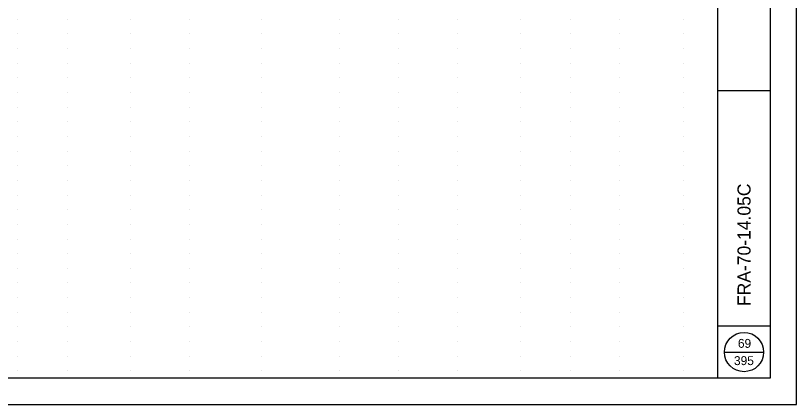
# Model space of a CAD drawing. Extents: x -15.4 to 18.6, y -12.6 to 9.4.
# Drawn here: x 3.72 to 18.64, y -12.61 to -5.18 of the extents above; entities that cross this region are included whole.
import ezdxf

# ---------------------------------------------------------------- set-up
doc = ezdxf.new("R2010")
doc.units = 0
for name, color, linetype in [('SH_Border', 7, 'Continuous'), ('SH_Cut_Line', 7, 'Continuous'), ('SH_Data', 7, 'Continuous')]:
    doc.layers.add(name, color=color, linetype=linetype)

msp = doc.modelspace()

# ---------------------------------------------------------------- linework, layer by layer
at = {"layer": 'SH_Border'}
for p, q in [((17.143, -12.112), (17.143, 8.888)), ((17.143, -6.612), (18.143, -6.612)), ((17.143, -11.112), (18.143, -11.112))]:
    msp.add_line(p, q, dxfattribs=at)
msp.add_lwpolyline([(-13.357, 8.888), (18.143, 8.888), (18.143, -12.112), (-13.357, -12.112)], close=True, dxfattribs=at)
at = {"layer": 'SH_Cut_Line'}
msp.add_lwpolyline([(-15.357, -12.612), (18.643, -12.612), (18.643, 9.388), (-15.357, 9.388)], close=True, dxfattribs=at)
at = {"layer": 'SH_Data'}
for p, q in [((3.768, -5.252), (3.768, -5.252)), ((4.718, -5.252), (4.718, -5.252)), ((5.918, -5.252), (5.918, -5.252)), ((7.043, -5.252), (7.043, -5.252)), ((8.418, -5.252), (8.418, -5.252)), ((9.918, -5.252), (9.918, -5.252)), ((11.043, -5.252), (11.043, -5.252)), ((12.168, -5.252), (12.168, -5.252)), ((13.368, -5.252), (13.368, -5.252)), ((14.318, -5.252), (14.318, -5.252)), ((15.268, -5.252), (15.268, -5.252)), ((16.493, -5.252), (16.493, -5.252)), ((3.768, -5.532), (3.768, -5.532)), ((4.718, -5.532), (4.718, -5.532)), ((5.918, -5.532), (5.918, -5.532)), ((7.043, -5.532), (7.043, -5.532)), ((8.418, -5.532), (8.418, -5.532)), ((9.918, -5.532), (9.918, -5.532)), ((11.043, -5.532), (11.043, -5.532)), ((12.168, -5.532), (12.168, -5.532)), ((13.368, -5.532), (13.368, -5.532)), ((14.318, -5.532), (14.318, -5.532)), ((15.268, -5.532), (15.268, -5.532)), ((16.493, -5.532), (16.493, -5.532)), ((3.768, -5.812), (3.768, -5.812)), ((4.718, -5.812), (4.718, -5.812)), ((5.918, -5.812), (5.918, -5.812)), ((7.043, -5.812), (7.043, -5.812)), ((8.418, -5.812), (8.418, -5.812)), ((9.918, -5.812), (9.918, -5.812)), ((11.043, -5.812), (11.043, -5.812)), ((12.168, -5.812), (12.168, -5.812)), ((13.368, -5.812), (13.368, -5.812)), ((14.318, -5.812), (14.318, -5.812)), ((15.268, -5.812), (15.268, -5.812)), ((16.493, -5.812), (16.493, -5.812)), ((3.768, -6.092), (3.768, -6.092)), ((4.718, -6.092), (4.718, -6.092)), ((5.918, -6.092), (5.918, -6.092)), ((7.043, -6.092), (7.043, -6.092)), ((8.418, -6.092), (8.418, -6.092)), ((9.918, -6.092), (9.918, -6.092)), ((11.043, -6.092), (11.043, -6.092)), ((12.168, -6.092), (12.168, -6.092)), ((13.368, -6.092), (13.368, -6.092)), ((14.318, -6.092), (14.318, -6.092)), ((15.268, -6.092), (15.268, -6.092)), ((16.493, -6.092), (16.493, -6.092)), ((3.768, -6.372), (3.768, -6.372)), ((4.718, -6.372), (4.718, -6.372)), ((5.918, -6.372), (5.918, -6.372)), ((7.043, -6.372), (7.043, -6.372)), ((8.418, -6.372), (8.418, -6.372)), ((9.918, -6.372), (9.918, -6.372)), ((11.043, -6.372), (11.043, -6.372)), ((12.168, -6.372), (12.168, -6.372)), ((13.368, -6.372), (13.368, -6.372)), ((14.318, -6.372), (14.318, -6.372)), ((15.268, -6.372), (15.268, -6.372)), ((16.493, -6.372), (16.493, -6.372)), ((3.768, -6.652), (3.768, -6.652)), ((4.718, -6.652), (4.718, -6.652)), ((5.918, -6.652), (5.918, -6.652)), ((7.043, -6.652), (7.043, -6.652)), ((8.418, -6.652), (8.418, -6.652)), ((9.918, -6.652), (9.918, -6.652)), ((11.043, -6.652), (11.043, -6.652)), ((12.168, -6.652), (12.168, -6.652)), ((13.368, -6.652), (13.368, -6.652)), ((14.318, -6.652), (14.318, -6.652)), ((15.268, -6.652), (15.268, -6.652)), ((16.493, -6.652), (16.493, -6.652)), ((3.768, -6.932), (3.768, -6.932)), ((4.718, -6.932), (4.718, -6.932)), ((5.918, -6.932), (5.918, -6.932)), ((7.043, -6.932), (7.043, -6.932)), ((8.418, -6.932), (8.418, -6.932)), ((9.918, -6.932), (9.918, -6.932)), ((11.043, -6.932), (11.043, -6.932)), ((12.168, -6.932), (12.168, -6.932)), ((13.368, -6.932), (13.368, -6.932)), ((14.318, -6.932), (14.318, -6.932)), ((15.268, -6.932), (15.268, -6.932)), ((16.493, -6.932), (16.493, -6.932)), ((3.768, -7.212), (3.768, -7.212)), ((4.718, -7.212), (4.718, -7.212)), ((5.918, -7.212), (5.918, -7.212)), ((7.043, -7.212), (7.043, -7.212)), ((8.418, -7.212), (8.418, -7.212)), ((9.918, -7.212), (9.918, -7.212)), ((11.043, -7.212), (11.043, -7.212)), ((12.168, -7.212), (12.168, -7.212)), ((13.368, -7.212), (13.368, -7.212)), ((14.318, -7.212), (14.318, -7.212)), ((15.268, -7.212), (15.268, -7.212)), ((16.493, -7.212), (16.493, -7.212)), ((3.768, -7.492), (3.768, -7.492)), ((4.718, -7.492), (4.718, -7.492)), ((5.918, -7.492), (5.918, -7.492)), ((7.043, -7.492), (7.043, -7.492)), ((8.418, -7.492), (8.418, -7.492)), ((9.918, -7.492), (9.918, -7.492)), ((11.043, -7.492), (11.043, -7.492)), ((12.168, -7.492), (12.168, -7.492)), ((13.368, -7.492), (13.368, -7.492)), ((14.318, -7.492), (14.318, -7.492)), ((15.268, -7.492), (15.268, -7.492)), ((16.493, -7.492), (16.493, -7.492)), ((3.768, -7.772), (3.768, -7.772)), ((4.718, -7.772), (4.718, -7.772)), ((5.918, -7.772), (5.918, -7.772)), ((7.043, -7.772), (7.043, -7.772)), ((8.418, -7.772), (8.418, -7.772)), ((9.918, -7.772), (9.918, -7.772)), ((11.043, -7.772), (11.043, -7.772)), ((12.168, -7.772), (12.168, -7.772)), ((13.368, -7.772), (13.368, -7.772)), ((14.318, -7.772), (14.318, -7.772)), ((15.268, -7.772), (15.268, -7.772)), ((16.493, -7.772), (16.493, -7.772)), ((3.768, -8.052), (3.768, -8.052)), ((4.718, -8.052), (4.718, -8.052)), ((5.918, -8.052), (5.918, -8.052)), ((7.043, -8.052), (7.043, -8.052)), ((8.418, -8.052), (8.418, -8.052)), ((9.918, -8.052), (9.918, -8.052)), ((11.043, -8.052), (11.043, -8.052)), ((12.168, -8.052), (12.168, -8.052)), ((13.368, -8.052), (13.368, -8.052)), ((14.318, -8.052), (14.318, -8.052)), ((15.268, -8.052), (15.268, -8.052)), ((16.493, -8.052), (16.493, -8.052)), ((3.768, -8.332), (3.768, -8.332)), ((4.718, -8.332), (4.718, -8.332)), ((5.918, -8.332), (5.918, -8.332)), ((7.043, -8.332), (7.043, -8.332)), ((8.418, -8.332), (8.418, -8.332)), ((9.918, -8.332), (9.918, -8.332)), ((11.043, -8.332), (11.043, -8.332)), ((12.168, -8.332), (12.168, -8.332)), ((13.368, -8.332), (13.368, -8.332)), ((14.318, -8.332), (14.318, -8.332)), ((15.268, -8.332), (15.268, -8.332)), ((16.493, -8.332), (16.493, -8.332)), ((3.768, -8.612), (3.768, -8.612)), ((4.718, -8.612), (4.718, -8.612)), ((5.918, -8.612), (5.918, -8.612)), ((7.043, -8.612), (7.043, -8.612)), ((8.418, -8.612), (8.418, -8.612)), ((9.918, -8.612), (9.918, -8.612)), ((11.043, -8.612), (11.043, -8.612)), ((12.168, -8.612), (12.168, -8.612)), ((13.368, -8.612), (13.368, -8.612)), ((14.318, -8.612), (14.318, -8.612)), ((15.268, -8.612), (15.268, -8.612)), ((16.493, -8.612), (16.493, -8.612)), ((3.768, -8.892), (3.768, -8.892)), ((4.718, -8.892), (4.718, -8.892)), ((5.918, -8.892), (5.918, -8.892)), ((7.043, -8.892), (7.043, -8.892)), ((8.418, -8.892), (8.418, -8.892)), ((9.918, -8.892), (9.918, -8.892)), ((11.043, -8.892), (11.043, -8.892)), ((12.168, -8.892), (12.168, -8.892)), ((13.368, -8.892), (13.368, -8.892)), ((14.318, -8.892), (14.318, -8.892)), ((15.268, -8.892), (15.268, -8.892)), ((16.493, -8.892), (16.493, -8.892)), ((3.768, -9.172), (3.768, -9.172)), ((4.718, -9.172), (4.718, -9.172)), ((5.918, -9.172), (5.918, -9.172)), ((7.043, -9.172), (7.043, -9.172)), ((8.418, -9.172), (8.418, -9.172)), ((9.918, -9.172), (9.918, -9.172)), ((11.043, -9.172), (11.043, -9.172)), ((12.168, -9.172), (12.168, -9.172)), ((13.368, -9.172), (13.368, -9.172)), ((14.318, -9.172), (14.318, -9.172)), ((15.268, -9.172), (15.268, -9.172)), ((16.493, -9.172), (16.493, -9.172)), ((3.768, -9.452), (3.768, -9.452)), ((4.718, -9.452), (4.718, -9.452)), ((5.918, -9.452), (5.918, -9.452)), ((7.043, -9.452), (7.043, -9.452)), ((8.418, -9.452), (8.418, -9.452)), ((9.918, -9.452), (9.918, -9.452)), ((11.043, -9.452), (11.043, -9.452)), ((12.168, -9.452), (12.168, -9.452)), ((13.368, -9.452), (13.368, -9.452)), ((14.318, -9.452), (14.318, -9.452)), ((15.268, -9.452), (15.268, -9.452)), ((16.493, -9.452), (16.493, -9.452)), ((3.768, -9.732), (3.768, -9.732)), ((4.718, -9.732), (4.718, -9.732)), ((5.918, -9.732), (5.918, -9.732)), ((7.043, -9.732), (7.043, -9.732)), ((8.418, -9.732), (8.418, -9.732)), ((9.918, -9.732), (9.918, -9.732)), ((11.043, -9.732), (11.043, -9.732)), ((12.168, -9.732), (12.168, -9.732)), ((13.368, -9.732), (13.368, -9.732)), ((14.318, -9.732), (14.318, -9.732)), ((15.268, -9.732), (15.268, -9.732)), ((16.493, -9.732), (16.493, -9.732)), ((3.768, -10.012), (3.768, -10.012)), ((4.718, -10.012), (4.718, -10.012)), ((5.918, -10.012), (5.918, -10.012)), ((7.043, -10.012), (7.043, -10.012)), ((8.418, -10.012), (8.418, -10.012)), ((9.918, -10.012), (9.918, -10.012)), ((11.043, -10.012), (11.043, -10.012)), ((12.168, -10.012), (12.168, -10.012)), ((13.368, -10.012), (13.368, -10.012)), ((14.318, -10.012), (14.318, -10.012)), ((15.268, -10.012), (15.268, -10.012)), ((16.493, -10.012), (16.493, -10.012)), ((3.768, -10.292), (3.768, -10.292)), ((4.718, -10.292), (4.718, -10.292)), ((5.918, -10.292), (5.918, -10.292)), ((7.043, -10.292), (7.043, -10.292)), ((8.418, -10.292), (8.418, -10.292)), ((9.918, -10.292), (9.918, -10.292)), ((11.043, -10.292), (11.043, -10.292)), ((12.168, -10.292), (12.168, -10.292)), ((13.368, -10.292), (13.368, -10.292)), ((14.318, -10.292), (14.318, -10.292)), ((15.268, -10.292), (15.268, -10.292)), ((16.493, -10.292), (16.493, -10.292)), ((3.768, -10.572), (3.768, -10.572)), ((4.718, -10.572), (4.718, -10.572)), ((5.918, -10.572), (5.918, -10.572)), ((7.043, -10.572), (7.043, -10.572)), ((8.418, -10.572), (8.418, -10.572)), ((9.918, -10.572), (9.918, -10.572)), ((11.043, -10.572), (11.043, -10.572)), ((12.168, -10.572), (12.168, -10.572)), ((13.368, -10.572), (13.368, -10.572)), ((14.318, -10.572), (14.318, -10.572)), ((15.268, -10.572), (15.268, -10.572)), ((16.493, -10.572), (16.493, -10.572)), ((3.768, -10.852), (3.768, -10.852)), ((4.718, -10.852), (4.718, -10.852)), ((5.918, -10.852), (5.918, -10.852)), ((7.043, -10.852), (7.043, -10.852)), ((8.418, -10.852), (8.418, -10.852)), ((9.918, -10.852), (9.918, -10.852)), ((11.043, -10.852), (11.043, -10.852)), ((12.168, -10.852), (12.168, -10.852)), ((13.368, -10.852), (13.368, -10.852)), ((14.318, -10.852), (14.318, -10.852)), ((15.268, -10.852), (15.268, -10.852)), ((16.493, -10.852), (16.493, -10.852)), ((3.768, -11.132), (3.768, -11.132)), ((4.718, -11.132), (4.718, -11.132)), ((5.918, -11.132), (5.918, -11.132)), ((7.043, -11.132), (7.043, -11.132)), ((8.418, -11.132), (8.418, -11.132)), ((9.918, -11.132), (9.918, -11.132)), ((11.043, -11.132), (11.043, -11.132)), ((12.168, -11.132), (12.168, -11.132)), ((13.368, -11.132), (13.368, -11.132)), ((14.318, -11.132), (14.318, -11.132)), ((15.268, -11.132), (15.268, -11.132)), ((16.493, -11.132), (16.493, -11.132)), ((3.768, -11.412), (3.768, -11.412)), ((4.718, -11.412), (4.718, -11.412)), ((5.918, -11.412), (5.918, -11.412)), ((7.043, -11.412), (7.043, -11.412)), ((8.418, -11.412), (8.418, -11.412)), ((9.918, -11.412), (9.918, -11.412)), ((11.043, -11.412), (11.043, -11.412)), ((12.168, -11.412), (12.168, -11.412)), ((13.368, -11.412), (13.368, -11.412)), ((14.318, -11.412), (14.318, -11.412)), ((15.268, -11.412), (15.268, -11.412)), ((16.493, -11.412), (16.493, -11.412)), ((17.268, -11.612), (18.018, -11.612)), ((3.768, -11.692), (3.768, -11.692)), ((4.718, -11.692), (4.718, -11.692)), ((5.918, -11.692), (5.918, -11.692)), ((7.043, -11.692), (7.043, -11.692)), ((8.418, -11.692), (8.418, -11.692)), ((9.918, -11.692), (9.918, -11.692)), ((11.043, -11.692), (11.043, -11.692)), ((12.168, -11.692), (12.168, -11.692)), ((13.368, -11.692), (13.368, -11.692)), ((14.318, -11.692), (14.318, -11.692)), ((15.268, -11.692), (15.268, -11.692)), ((16.493, -11.692), (16.493, -11.692)), ((3.768, -11.972), (3.768, -11.972)), ((4.718, -11.972), (4.718, -11.972)), ((5.918, -11.972), (5.918, -11.972)), ((7.043, -11.972), (7.043, -11.972)), ((8.418, -11.972), (8.418, -11.972)), ((9.918, -11.972), (9.918, -11.972)), ((11.043, -11.972), (11.043, -11.972)), ((12.168, -11.972), (12.168, -11.972)), ((13.368, -11.972), (13.368, -11.972)), ((14.318, -11.972), (14.318, -11.972)), ((15.268, -11.972), (15.268, -11.972)), ((16.493, -11.972), (16.493, -11.972))]:
    msp.add_line(p, q, dxfattribs=at)
msp.add_circle((17.643, -11.612), 0.375, dxfattribs=at)

# ---------------------------------------------------------------- texts
msp.add_text(' FRA-70-14.05C  ', height=0.25, rotation=90, dxfattribs=at).set_placement((17.768, -10.825))
for s, p in [('69', (17.526, -11.531)), ('395', (17.451, -11.861))]:
    msp.add_text(s, height=0.17, dxfattribs=at).set_placement(p)

doc.saveas('drawing.dxf')
